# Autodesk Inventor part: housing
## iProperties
Created: 2010-11
Part Number: housing
Document SubType Name: Modeling
Designer: ROBERT
Density: 1 g/cm^3
Author: ROBERT
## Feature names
1. Extrusion1
2. Extrusion2
